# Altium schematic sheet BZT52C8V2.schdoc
size 127 x 101 mm
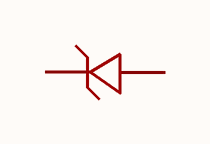
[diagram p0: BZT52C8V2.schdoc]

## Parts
D?  bzt52c8v2 wd  [SOD-123_L2.8-W1.8-LS3.7-RD]  (value not drawn)

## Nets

Not connected (* = marked no-connect by the designer): D? 1(K) 2(A)

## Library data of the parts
D? = bzt52c8v2 wd: 二极管配置:1个独立式;稳压值(标称值):8.2V;稳压值(范围):7.7V~8.7V;耗散功率(Pd):500mW;; Manufacturer: CJ(江苏长电/长晶); AddInBom: yes; ModelId: 7884390a25fb4c08947731ebfba7e3f8; ModelTransform: 144.8816,62.992,0,0,0,0,0,0,0; Diode Configuration: 1个独立式; Zener Voltage(Nom): 8.2V; Reverse Leakage Current (Ir): 700nA@5V; Pd - Power Dissipation: 500mW; Impedance(Zzt): 15Ω; Impedance(Zzk): 80Ω; Operating Junction Temperature Range: -55℃~+150℃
